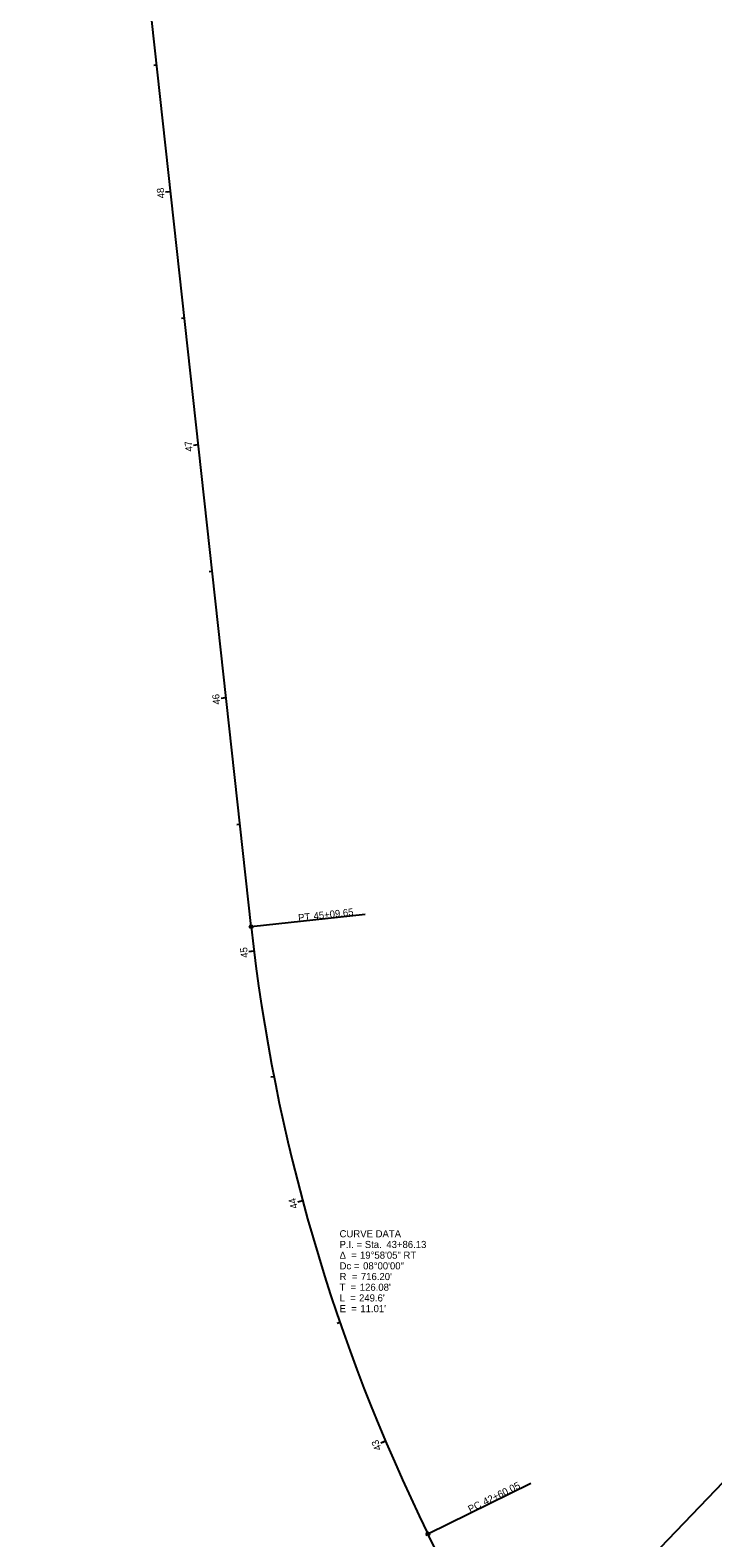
# Model space of a CAD drawing. Extents: x 1363001 to 1363920, y 487582 to 489802.
# Drawn here: x 1363080 to 1363348, y 488595 to 489187 of the extents above; entities that cross this region are included whole.
import ezdxf

# ---------------------------------------------------------------- set-up
doc = ezdxf.new("R2010")
doc.units = 0
for name, color, linetype in [('BR_X_SV_Bottom_of_Beam_Text', 7, 'Continuous'), ('BR_X_SV_Shot_Marker', 7, 'Continuous'), ('DR_X_Elev_Flow', 7, 'Continuous'), ('PV_X_Curb', 7, 'Continuous'), ('RD_X_GR_Rt', 7, 'Continuous'), ('SG_X_PullBox', 7, 'Continuous'), ('SV_P_Control_Cells_Set', 7, 'Continuous'), ('SV_X_Shot_Marker', 7, 'Continuous'), ('SV_X_Text_Comment', 7, 'Continuous'), ('SV_X_Text_Name', 7, 'Continuous'), ('UT_X_Electric', 7, 'Continuous'), ('UT_X_Water', 7, 'Continuous')]:
    doc.layers.add(name, color=color, linetype=linetype)

msp = doc.modelspace()

# ---------------------------------------------------------------- linework, layer by layer
at = {"layer": 'BR_X_SV_Bottom_of_Beam_Text'}
for p, q in [((1363166.9, 488834.82), (1363211.64, 488839.72)), ((1363236.31, 488596.38), (1363276.68, 488616.26))]:
    msp.add_line(p, q, dxfattribs=at)
for centre in [(1363166.9, 488834.82), (1363236.31, 488596.38)]:
    msp.add_circle(centre, 0.6, dxfattribs=at)
at = {"layer": 'BR_X_SV_Shot_Marker'}
for p, q in [((1363129.88, 489173.15), (1363128.68, 489173.02)), ((1363135.31, 489123.45), (1363133.33, 489123.23)), ((1363140.75, 489073.75), (1363139.56, 489073.62)), ((1363146.19, 489024.04), (1363144.21, 489023.83)), ((1363151.63, 488974.34), (1363150.44, 488974.21)), ((1363157.07, 488924.64), (1363155.09, 488924.42)), ((1363162.51, 488874.93), (1363161.32, 488874.8)), ((1363168.02, 488825.24), (1363166.03, 488824.99)), ((1363175.85, 488775.87), (1363174.67, 488775.64)), ((1363187.11, 488727.16), (1363185.18, 488726.64)), ((1363201.74, 488679.36), (1363200.61, 488678.97)), ((1363219.67, 488632.69), (1363217.83, 488631.91))]:
    msp.add_line(p, q, dxfattribs=at)
at = {"layer": 'PV_X_Curb'}
for p, q in [((1363166.9, 488834.82), (1363211.64, 488839.72)), ((1363236.31, 488596.38), (1363276.68, 488616.26))]:
    msp.add_line(p, q, dxfattribs=at)
for centre in [(1363166.9, 488834.82), (1363236.31, 488596.38)]:
    msp.add_circle(centre, 0.6, dxfattribs=at)
at = {"layer": 'RD_X_GR_Rt'}
msp.add_line((1363168.02, 488825.24), (1363166.83, 488825.09), dxfattribs=at)
at = {"layer": 'SG_X_PullBox'}
for p, q in [((1363135.31, 489123.45), (1363134.12, 489123.32)), ((1363146.19, 489024.04), (1363145, 489023.91)), ((1363157.07, 488924.64), (1363155.88, 488924.51)), ((1363168.02, 488825.24), (1363166.03, 488824.99)), ((1363187.11, 488727.16), (1363185.95, 488726.85)), ((1363219.67, 488632.69), (1363218.57, 488632.23))]:
    msp.add_line(p, q, dxfattribs=at)
at = {"layer": 'SV_X_Shot_Marker'}
msp.add_line((1363166.9, 488834.82), (1363084.73, 489585.69), dxfattribs=at)
msp.add_arc((1363878.85, 488912.74), 716.2, 186.24567, 206.21359, dxfattribs=at)
at = {"layer": 'SV_X_Text_Comment'}
for p, q in [((1363166.9, 488834.82), (1363084.73, 489585.69)), ((1363080.13, 488332.82), (1363449.43, 488718.12)), ((1363269.04, 488529.91), (1363236.31, 488596.38))]:
    msp.add_line(p, q, dxfattribs=at)
msp.add_arc((1363878.85, 488912.74), 716.2, 186.24567, 206.21359, dxfattribs=at)
at = {"layer": 'SV_X_Text_Name'}
for p, q in [((1363235.64, 488595.71), (1363236.98, 488597.05)), ((1363235.64, 488597.05), (1363236.98, 488595.71))]:
    msp.add_line(p, q, dxfattribs=at)
at = {"layer": 'UT_X_Water'}
for p, q in [((1363166.9, 488834.82), (1363211.64, 488839.72)), ((1363236.31, 488596.38), (1363276.68, 488616.26))]:
    msp.add_line(p, q, dxfattribs=at)
for centre in [(1363166.9, 488834.82), (1363236.31, 488596.38)]:
    msp.add_circle(centre, 0.6, dxfattribs=at)

# ---------------------------------------------------------------- texts
at = {"layer": 'BR_X_SV_Bottom_of_Beam_Text'}
for s, rotation, p in [('PT', 6.24567, (1363185.5, 488836.91)), ('45+09.65', 6.24567, (1363191.55, 488837.57)), ('42+60.05', 26.21359, (1363258.74, 488607.47)), ('PC', 26.21359, (1363252.89, 488604.59))]:
    msp.add_text(s, height=2.8, rotation=rotation, dxfattribs=at).set_placement(p)
at = {"layer": 'BR_X_SV_Shot_Marker'}
for s, rotation, p in [('48', 96.24567, (1363133.02, 489120.99)), ('47', 96.24567, (1363143.95, 489021.53)), ('46', 96.24567, (1363154.78, 488922.18)), ('45', 97.01766, (1363165.76, 488822.74)), ('44', 105.01763, (1363185.26, 488724.43)), ('43', 113.0176, (1363218.18, 488629.7))]:
    msp.add_text(s, height=2.8, rotation=rotation, dxfattribs=at).set_placement(p)
at = {"layer": 'DR_X_Elev_Flow'}
for s, p in [('CURVE DATA', (1363201.61, 488712.8)), ('P.I. = Sta. ', (1363201.61, 488708.6)), ('43+86.13', (1363219.97, 488708.6)), ('Δ  = ', (1363201.61, 488704.4)), ('Dc = ', (1363201.61, 488700.2)), ('19°58\'05" RT', (1363209.63, 488704.4)), ('08°00\'00"', (1363210.85, 488700.2)), ('R  = ', (1363201.61, 488696)), ("716.20'", (1363209.97, 488696)), ('T  = ', (1363201.61, 488691.8)), ('L  = ', (1363201.61, 488687.6)), ("249.6'", (1363209.25, 488687.6)), ("126.08'", (1363209.54, 488691.8)), ('E  = ', (1363201.61, 488683.4)), ("11.01'", (1363209.76, 488683.4))]:
    msp.add_text(s, height=2.8, dxfattribs=at).set_placement(p)
at = {"layer": 'PV_X_Curb'}
for s, rotation, p in [('PT', 6.24567, (1363185.5, 488836.91)), ('45+09.65', 6.24567, (1363191.55, 488837.57)), ('42+60.05', 26.21359, (1363258.74, 488607.47)), ('PC', 26.21359, (1363252.89, 488604.59))]:
    msp.add_text(s, height=2.8, rotation=rotation, dxfattribs=at).set_placement(p)
at = {"layer": 'SG_X_PullBox'}
msp.add_text('45', height=2.8, rotation=97.01766, dxfattribs=at).set_placement((1363165.76, 488822.74))
at = {"layer": 'SV_P_Control_Cells_Set'}
for s, p in [('CURVE DATA', (1363201.61, 488712.8)), ('P.I. = Sta. ', (1363201.61, 488708.6)), ('43+86.13', (1363219.97, 488708.6)), ('Δ  = ', (1363201.61, 488704.4)), ('Dc = ', (1363201.61, 488700.2)), ('19°58\'05" RT', (1363209.63, 488704.4)), ('08°00\'00"', (1363210.85, 488700.2)), ('R  = ', (1363201.61, 488696)), ("716.20'", (1363209.97, 488696)), ('T  = ', (1363201.61, 488691.8)), ('L  = ', (1363201.61, 488687.6)), ("249.6'", (1363209.25, 488687.6)), ("126.08'", (1363209.54, 488691.8)), ('E  = ', (1363201.61, 488683.4)), ("11.01'", (1363209.76, 488683.4))]:
    msp.add_text(s, height=2.8, dxfattribs=at).set_placement(p)
at = {"layer": 'UT_X_Electric'}
for s, p in [('CURVE DATA', (1363201.61, 488712.8)), ('P.I. = Sta. ', (1363201.61, 488708.6)), ('43+86.13', (1363219.97, 488708.6)), ('Δ  = ', (1363201.61, 488704.4)), ('Dc = ', (1363201.61, 488700.2)), ('19°58\'05" RT', (1363209.63, 488704.4)), ('08°00\'00"', (1363210.85, 488700.2)), ('R  = ', (1363201.61, 488696)), ("716.20'", (1363209.97, 488696)), ('T  = ', (1363201.61, 488691.8)), ('L  = ', (1363201.61, 488687.6)), ("249.6'", (1363209.25, 488687.6)), ("126.08'", (1363209.54, 488691.8)), ('E  = ', (1363201.61, 488683.4)), ("11.01'", (1363209.76, 488683.4))]:
    msp.add_text(s, height=2.8, dxfattribs=at).set_placement(p)
at = {"layer": 'UT_X_Water'}
for s, rotation, p in [('PT', 6.24567, (1363185.5, 488836.91)), ('45+09.65', 6.24567, (1363191.55, 488837.57)), ('42+60.05', 26.21359, (1363258.74, 488607.47)), ('PC', 26.21359, (1363252.89, 488604.59))]:
    msp.add_text(s, height=2.8, rotation=rotation, dxfattribs=at).set_placement(p)

doc.saveas('drawing.dxf')
